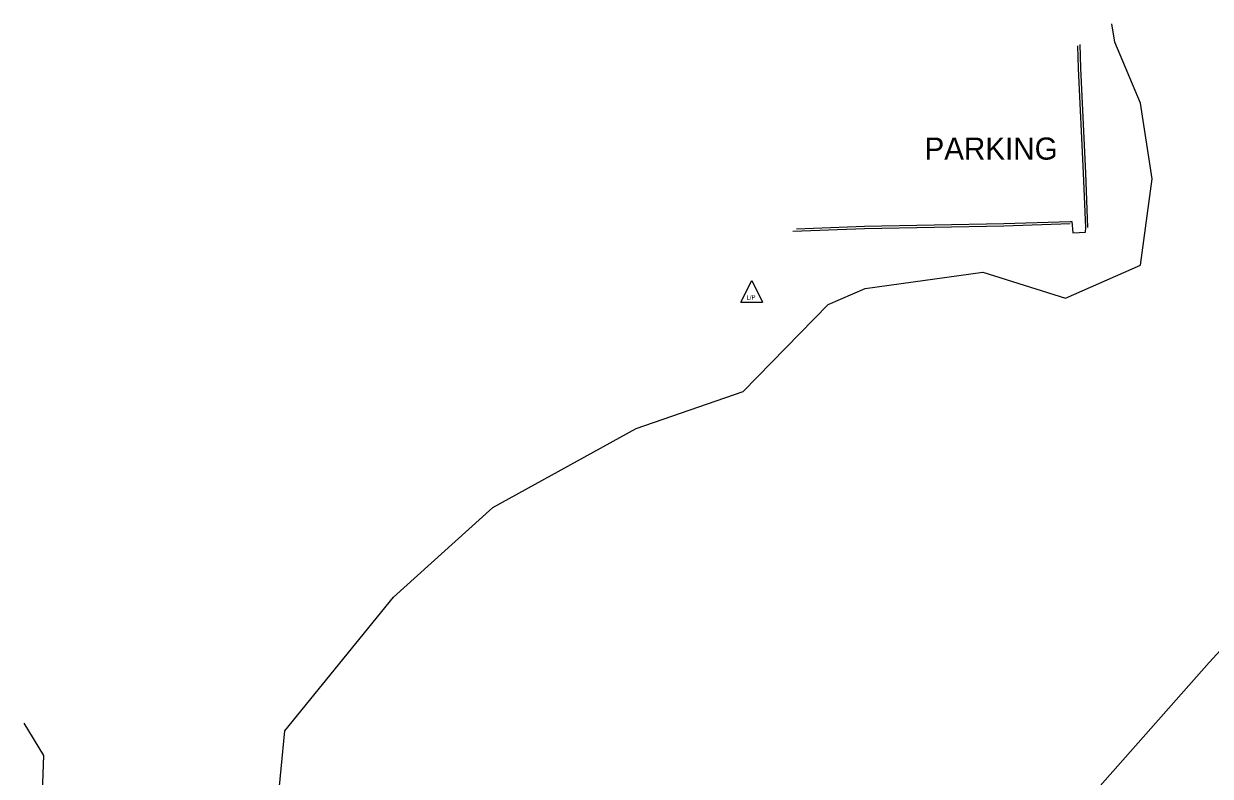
# Model space of a CAD drawing. Extents: x 1901471 to 1963503, y 756461 to 799997.
# Drawn here: x 1923676.8 to 1923945, y 769757.2 to 769927.5 of the extents above; entities that cross this region are included whole.
import ezdxf

# ---------------------------------------------------------------- set-up
doc = ezdxf.new("R2010")
doc.units = 0
for name, color, linetype in [('RD_EX_Conc', 7, 'Continuous'), ('RD_EX_Road', 7, 'Continuous'), ('RD_EX_UT', 7, 'Continuous'), ('RD_EX_VEG', 7, 'Continuous')]:
    doc.layers.add(name, color=color, linetype=linetype)

# ---------------------------------------------------------------- blocks, each defined once
blk = doc.blocks.new('LP')
at = {"layer": 'RD_EX_UT'}
for p, q in [((-5, -3.72), (0, 6.28)), ((0, 6.28), (5, -3.72)), ((-5, -3.72), (5, -3.72))]:
    blk.add_line(p, q, dxfattribs=at)
blk.add_text('L/P', height=2, dxfattribs=at).set_placement((-2.4, -2.44))

msp = doc.modelspace()

# ---------------------------------------------------------------- linework, layer by layer
at = {"layer": 'RD_EX_Conc'}
for points in [[(1923917.38, 769881.4), (1923916.89, 769893.69), (1923915.79, 769917.38), (1923915.63, 769922.79)], [(1923850.64, 769880.51), (1923866.85, 769881.17), (1923898.35, 769881.75), (1923913.38, 769882.25)]]:
    msp.add_lwpolyline(points, dxfattribs=at)
at = {"layer": 'RD_EX_Road'}
msp.add_lwpolyline([(1923851.47, 769881.04), (1923866.84, 769881.67), (1923898.34, 769882.25), (1923913.36, 769882.75), (1923913.71, 769882.72), (1923913.99, 769880.14), (1923916.85, 769880.33), (1923916.88, 769881.39), (1923916.39, 769893.67), (1923915.29, 769917.36), (1923915.14, 769922.47)], dxfattribs=at)
at = {"layer": 'RD_EX_VEG'}
for points in [[(1923735.84, 769767.52), (1923760.39, 769797.71), (1923782.87, 769818.02), (1923815.27, 769835.92), (1923839.41, 769844.25), (1923858.68, 769863.91), (1923867.01, 769867.54), (1923893.59, 769871.29), (1923912.33, 769865.39), (1923929.26, 769872.81), (1923931.92, 769892.34), (1923929.26, 769909.47), (1923923.49, 769923.3), (1923922.82, 769927.47)], [(1923970.77, 769811.2), (1923944.76, 769782.96), (1923913.8, 769747.86), (1923879.06, 769714.1), (1923856.07, 769693.46), (1923838.26, 769681.28), (1923806.32, 769662.95), (1923779.65, 769649.65), (1923760.46, 769643.32), (1923750.72, 769646.92), (1923738.41, 769660.54), (1923737.54, 769669.62), (1923739.83, 769680.74), (1923731.83, 769693.48), (1923733.47, 769709.07), (1923731.55, 769722.19), (1923731.82, 769732.42), (1923734.18, 769750.27), (1923735.84, 769767.52)], [(1923676.79, 769769.26), (1923681.26, 769761.89), (1923680.69, 769745.28)]]:
    msp.add_lwpolyline(points, dxfattribs=at)

# ---------------------------------------------------------------- block references
at = {"layer": 'RD_EX_UT', "xscale": 0.4921259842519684, "yscale": 0.4921259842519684}
msp.add_blockref('LP', (1923841.37, 769866.27), dxfattribs=at)

# ---------------------------------------------------------------- texts
at = {"layer": 'RD_EX_Road'}
msp.add_text('PARKING', height=5, dxfattribs=at).set_placement((1923880.44, 769896.72))

doc.saveas('drawing.dxf')
